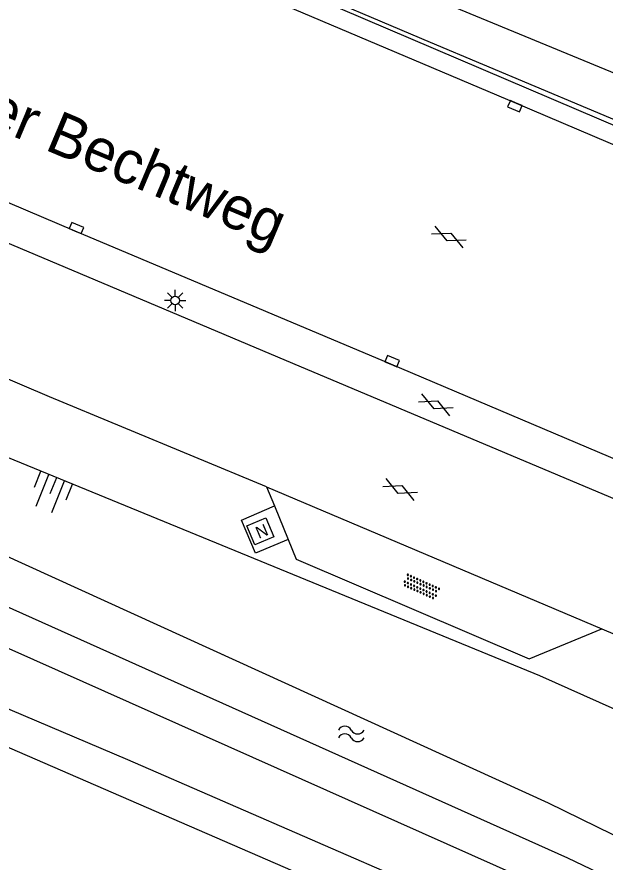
# Model space of a CAD drawing. Extents: x 136000 to 138005, y 398500 to 400500.
# Drawn here: x 136474.73 to 136509.2, y 399012.55 to 399062.04 of the extents above; entities that cross this region are included whole.
import ezdxf

# ---------------------------------------------------------------- set-up
doc = ezdxf.new("R2010")
doc.units = 0
for name, color, linetype in [('gg-afsc-faunaraster', 7, 'Continuous'), ('gg-anno-openbare ruimte label', 7, 'Continuous'), ('gg-knt-BGT kruinlijn', 7, 'Continuous'), ('gg-knt-verharding', 7, 'Continuous'), ('gg-kntw-bovenkant insteek waterloop', 7, 'Continuous'), ('gg-kntw-waterlijn', 7, 'Continuous'), ('gt-knt-geleideconstructie', 7, 'Continuous'), ('gt-symb-gesloten verharding', 7, 'Continuous'), ('gt-symb-kolk', 7, 'Continuous'), ('gt-symb-lichtmast', 7, 'Continuous'), ('gt-symb-nortonput', 7, 'Continuous'), ('gt-symb-overige verharding', 7, 'Continuous'), ('gt-symb-talud symbool', 7, 'Continuous'), ('gt-symb-watersymbool', 7, 'Continuous')]:
    doc.layers.add(name, color=color, linetype=linetype)

# ---------------------------------------------------------------- blocks, each defined once
blk = doc.blocks.new('gt0-LMAST')
at = {"layer": 'gt-symb-lichtmast'}
for p, q in [((-0.005, 0.246), (-0.005, 0.621)), ((-0.182, 0.173), (-0.447, 0.438)), ((0.172, 0.173), (0.437, 0.438)), ((-0.255, -0.004), (-0.63, -0.004)), ((-0.182, -0.181), (-0.447, -0.446)), ((-0.005, -0.254), (-0.005, -0.629)), ((0.437, -0.446), (0.172, -0.181)), ((0.245, -0.004), (0.62, -0.004))]:
    blk.add_line(p, q, dxfattribs=at)
blk.add_circle((-0.005, -0.004), 0.25, dxfattribs=at)
blk = doc.blocks.new('gt0-GESVH1')
at = {"layer": 'gt-symb-gesloten verharding'}
for p, q in [((-0.992, -0.261), (0.008, 0.239)), ((0.008, -0.261), (-0.992, 0.239)), ((0.008, 0.239), (1.008, -0.261)), ((1.008, 0.239), (0.008, -0.261))]:
    blk.add_line(p, q, dxfattribs=at)
blk = doc.blocks.new('gt0-KOLK')
at = {"layer": 'gt-symb-kolk'}
blk.add_lwpolyline([(0, 0), (0.375, 0), (0.375, 0.4), (-0.375, 0.4), (-0.375, 0), (0, 0)], dxfattribs=at)
blk = doc.blocks.new('gt0-OVH')
at = {"layer": 'gt-symb-overige verharding'}
for points in [[(-0.972, 0.298), (-0.967, 0.308), (-0.965, 0.319), (-0.966, 0.33), (-0.971, 0.34), (-0.978, 0.348), (-0.988, 0.353), (-0.999, 0.355), (-1.01, 0.354), (-1.02, 0.349), (-1.028, 0.342), (-1.033, 0.332), (-1.035, 0.321), (-1.034, 0.31), (-1.029, 0.3), (-1.022, 0.292), (-1.012, 0.287), (-1.001, 0.285), (-0.99, 0.286), (-0.98, 0.291)], [(-0.872, 0.106), (-0.867, 0.116), (-0.865, 0.126), (-0.866, 0.137), (-0.871, 0.147), (-0.878, 0.156), (-0.888, 0.161), (-0.899, 0.163), (-0.91, 0.162), (-0.92, 0.157), (-0.928, 0.15), (-0.933, 0.14), (-0.935, 0.129), (-0.934, 0.118), (-0.929, 0.108), (-0.922, 0.1), (-0.912, 0.095), (-0.901, 0.092), (-0.89, 0.094), (-0.88, 0.098)], [(-0.772, 0.298), (-0.767, 0.308), (-0.765, 0.319), (-0.766, 0.33), (-0.771, 0.34), (-0.778, 0.348), (-0.788, 0.353), (-0.799, 0.355), (-0.81, 0.354), (-0.82, 0.349), (-0.828, 0.342), (-0.833, 0.332), (-0.835, 0.321), (-0.834, 0.31), (-0.829, 0.3), (-0.822, 0.292), (-0.812, 0.287), (-0.801, 0.285), (-0.79, 0.286), (-0.78, 0.291)], [(-0.672, 0.106), (-0.667, 0.116), (-0.665, 0.126), (-0.666, 0.137), (-0.671, 0.147), (-0.678, 0.156), (-0.688, 0.161), (-0.699, 0.163), (-0.71, 0.162), (-0.72, 0.157), (-0.728, 0.15), (-0.733, 0.14), (-0.735, 0.129), (-0.734, 0.118), (-0.729, 0.108), (-0.722, 0.1), (-0.712, 0.095), (-0.701, 0.092), (-0.69, 0.094), (-0.68, 0.098)], [(-0.572, 0.298), (-0.567, 0.308), (-0.565, 0.319), (-0.566, 0.33), (-0.571, 0.34), (-0.578, 0.348), (-0.588, 0.353), (-0.599, 0.355), (-0.61, 0.354), (-0.62, 0.349), (-0.628, 0.342), (-0.633, 0.332), (-0.635, 0.321), (-0.634, 0.31), (-0.629, 0.3), (-0.622, 0.292), (-0.612, 0.287), (-0.601, 0.285), (-0.59, 0.286), (-0.58, 0.291)], [(-0.472, 0.106), (-0.467, 0.116), (-0.465, 0.126), (-0.466, 0.137), (-0.471, 0.147), (-0.478, 0.156), (-0.488, 0.161), (-0.499, 0.163), (-0.51, 0.162), (-0.52, 0.157), (-0.528, 0.15), (-0.533, 0.14), (-0.535, 0.129), (-0.534, 0.118), (-0.529, 0.108), (-0.522, 0.1), (-0.512, 0.095), (-0.501, 0.092), (-0.49, 0.094), (-0.48, 0.098)], [(-0.372, 0.298), (-0.367, 0.308), (-0.365, 0.319), (-0.366, 0.33), (-0.371, 0.34), (-0.378, 0.348), (-0.388, 0.353), (-0.399, 0.355), (-0.41, 0.354), (-0.42, 0.349), (-0.428, 0.342), (-0.433, 0.332), (-0.435, 0.321), (-0.434, 0.31), (-0.429, 0.3), (-0.422, 0.292), (-0.412, 0.287), (-0.401, 0.285), (-0.39, 0.286), (-0.38, 0.291)], [(-0.272, 0.106), (-0.267, 0.116), (-0.265, 0.126), (-0.266, 0.137), (-0.271, 0.147), (-0.278, 0.156), (-0.288, 0.161), (-0.299, 0.163), (-0.31, 0.162), (-0.32, 0.157), (-0.328, 0.15), (-0.333, 0.14), (-0.335, 0.129), (-0.334, 0.118), (-0.329, 0.108), (-0.322, 0.1), (-0.312, 0.095), (-0.301, 0.092), (-0.29, 0.094), (-0.28, 0.098)], [(-0.172, 0.298), (-0.167, 0.308), (-0.165, 0.319), (-0.166, 0.33), (-0.171, 0.34), (-0.178, 0.348), (-0.188, 0.353), (-0.199, 0.355), (-0.21, 0.354), (-0.22, 0.349), (-0.228, 0.342), (-0.233, 0.332), (-0.235, 0.321), (-0.234, 0.31), (-0.229, 0.3), (-0.222, 0.292), (-0.212, 0.287), (-0.201, 0.285), (-0.19, 0.286), (-0.18, 0.291)], [(-0.072, 0.106), (-0.067, 0.116), (-0.065, 0.126), (-0.066, 0.137), (-0.071, 0.147), (-0.078, 0.156), (-0.088, 0.161), (-0.099, 0.163), (-0.11, 0.162), (-0.12, 0.157), (-0.128, 0.15), (-0.133, 0.14), (-0.135, 0.129), (-0.134, 0.118), (-0.129, 0.108), (-0.122, 0.1), (-0.112, 0.095), (-0.101, 0.092), (-0.09, 0.094), (-0.08, 0.098)], [(0.028, 0.298), (0.033, 0.308), (0.035, 0.319), (0.034, 0.33), (0.029, 0.34), (0.022, 0.348), (0.012, 0.353), (0.001, 0.355), (-0.01, 0.354), (-0.02, 0.349), (-0.028, 0.342), (-0.033, 0.332), (-0.035, 0.321), (-0.034, 0.31), (-0.029, 0.3), (-0.022, 0.292), (-0.012, 0.287), (-0.001, 0.285), (0.01, 0.286), (0.02, 0.291)], [(0.128, 0.106), (0.133, 0.116), (0.135, 0.126), (0.134, 0.137), (0.129, 0.147), (0.122, 0.156), (0.112, 0.161), (0.101, 0.163), (0.09, 0.162), (0.08, 0.157), (0.072, 0.15), (0.067, 0.14), (0.065, 0.129), (0.066, 0.118), (0.071, 0.108), (0.078, 0.1), (0.088, 0.095), (0.099, 0.092), (0.11, 0.094), (0.12, 0.098)], [(0.228, 0.298), (0.233, 0.308), (0.235, 0.319), (0.234, 0.33), (0.229, 0.34), (0.222, 0.348), (0.212, 0.353), (0.201, 0.355), (0.19, 0.354), (0.18, 0.349), (0.172, 0.342), (0.167, 0.332), (0.165, 0.321), (0.166, 0.31), (0.171, 0.3), (0.178, 0.292), (0.188, 0.287), (0.199, 0.285), (0.21, 0.286), (0.22, 0.291)], [(0.328, 0.106), (0.333, 0.116), (0.335, 0.126), (0.334, 0.137), (0.329, 0.147), (0.322, 0.156), (0.312, 0.161), (0.301, 0.163), (0.29, 0.162), (0.28, 0.157), (0.272, 0.15), (0.267, 0.14), (0.265, 0.129), (0.266, 0.118), (0.271, 0.108), (0.278, 0.1), (0.288, 0.095), (0.299, 0.092), (0.31, 0.094), (0.32, 0.098)], [(0.428, 0.298), (0.433, 0.308), (0.435, 0.319), (0.434, 0.33), (0.429, 0.34), (0.422, 0.348), (0.412, 0.353), (0.401, 0.355), (0.39, 0.354), (0.38, 0.349), (0.372, 0.342), (0.367, 0.332), (0.365, 0.321), (0.366, 0.31), (0.371, 0.3), (0.378, 0.292), (0.388, 0.287), (0.399, 0.285), (0.41, 0.286), (0.42, 0.291)], [(0.528, 0.106), (0.533, 0.116), (0.535, 0.126), (0.534, 0.137), (0.529, 0.147), (0.522, 0.156), (0.512, 0.161), (0.501, 0.163), (0.49, 0.162), (0.48, 0.157), (0.472, 0.15), (0.467, 0.14), (0.465, 0.129), (0.466, 0.118), (0.471, 0.108), (0.478, 0.1), (0.488, 0.095), (0.499, 0.092), (0.51, 0.094), (0.52, 0.098)], [(0.628, 0.298), (0.633, 0.308), (0.635, 0.319), (0.634, 0.33), (0.629, 0.34), (0.622, 0.348), (0.612, 0.353), (0.601, 0.355), (0.59, 0.354), (0.58, 0.349), (0.572, 0.342), (0.567, 0.332), (0.565, 0.321), (0.566, 0.31), (0.571, 0.3), (0.578, 0.292), (0.588, 0.287), (0.599, 0.285), (0.61, 0.286), (0.62, 0.291)], [(0.728, 0.106), (0.733, 0.116), (0.735, 0.126), (0.734, 0.137), (0.729, 0.147), (0.722, 0.156), (0.712, 0.161), (0.701, 0.163), (0.69, 0.162), (0.68, 0.157), (0.672, 0.15), (0.667, 0.14), (0.665, 0.129), (0.666, 0.118), (0.671, 0.108), (0.678, 0.1), (0.688, 0.095), (0.699, 0.092), (0.71, 0.094), (0.72, 0.098)], [(0.828, 0.298), (0.833, 0.308), (0.835, 0.319), (0.834, 0.33), (0.829, 0.34), (0.822, 0.348), (0.812, 0.353), (0.801, 0.355), (0.79, 0.354), (0.78, 0.349), (0.772, 0.342), (0.767, 0.332), (0.765, 0.321), (0.766, 0.31), (0.771, 0.3), (0.778, 0.292), (0.788, 0.287), (0.799, 0.285), (0.81, 0.286), (0.82, 0.291)], [(0.928, 0.106), (0.933, 0.116), (0.935, 0.126), (0.934, 0.137), (0.929, 0.147), (0.922, 0.156), (0.912, 0.161), (0.901, 0.163), (0.89, 0.162), (0.88, 0.157), (0.872, 0.15), (0.867, 0.14), (0.865, 0.129), (0.866, 0.118), (0.871, 0.108), (0.878, 0.1), (0.888, 0.095), (0.899, 0.092), (0.91, 0.094), (0.92, 0.098)], [(1.028, 0.298), (1.033, 0.308), (1.035, 0.319), (1.034, 0.33), (1.029, 0.34), (1.022, 0.348), (1.012, 0.353), (1.001, 0.355), (0.99, 0.354), (0.98, 0.349), (0.972, 0.342), (0.967, 0.332), (0.965, 0.321), (0.966, 0.31), (0.971, 0.3), (0.978, 0.292), (0.988, 0.287), (0.999, 0.285), (1.01, 0.286), (1.02, 0.291)], [(-0.972, -0.142), (-0.967, -0.132), (-0.965, -0.121), (-0.966, -0.11), (-0.971, -0.1), (-0.978, -0.092), (-0.988, -0.087), (-0.999, -0.085), (-1.01, -0.086), (-1.02, -0.091), (-1.028, -0.098), (-1.033, -0.108), (-1.035, -0.119), (-1.034, -0.13), (-1.029, -0.14), (-1.022, -0.148), (-1.012, -0.153), (-1.001, -0.155), (-0.99, -0.154), (-0.98, -0.149)], [(-0.872, -0.334), (-0.867, -0.324), (-0.865, -0.314), (-0.866, -0.303), (-0.871, -0.293), (-0.878, -0.284), (-0.888, -0.279), (-0.899, -0.277), (-0.91, -0.278), (-0.92, -0.283), (-0.928, -0.29), (-0.933, -0.3), (-0.935, -0.311), (-0.934, -0.322), (-0.929, -0.332), (-0.922, -0.34), (-0.912, -0.345), (-0.901, -0.348), (-0.89, -0.346), (-0.88, -0.342)], [(-0.772, -0.142), (-0.767, -0.132), (-0.765, -0.121), (-0.766, -0.11), (-0.771, -0.1), (-0.778, -0.092), (-0.788, -0.087), (-0.799, -0.085), (-0.81, -0.086), (-0.82, -0.091), (-0.828, -0.098), (-0.833, -0.108), (-0.835, -0.119), (-0.834, -0.13), (-0.829, -0.14), (-0.822, -0.148), (-0.812, -0.153), (-0.801, -0.155), (-0.79, -0.154), (-0.78, -0.149)], [(-0.672, -0.334), (-0.667, -0.324), (-0.665, -0.314), (-0.666, -0.303), (-0.671, -0.293), (-0.678, -0.284), (-0.688, -0.279), (-0.699, -0.277), (-0.71, -0.278), (-0.72, -0.283), (-0.728, -0.29), (-0.733, -0.3), (-0.735, -0.311), (-0.734, -0.322), (-0.729, -0.332), (-0.722, -0.34), (-0.712, -0.345), (-0.701, -0.348), (-0.69, -0.346), (-0.68, -0.342)], [(-0.572, -0.142), (-0.567, -0.132), (-0.565, -0.121), (-0.566, -0.11), (-0.571, -0.1), (-0.578, -0.092), (-0.588, -0.087), (-0.599, -0.085), (-0.61, -0.086), (-0.62, -0.091), (-0.628, -0.098), (-0.633, -0.108), (-0.635, -0.119), (-0.634, -0.13), (-0.629, -0.14), (-0.622, -0.148), (-0.612, -0.153), (-0.601, -0.155), (-0.59, -0.154), (-0.58, -0.149)], [(-0.472, -0.334), (-0.467, -0.324), (-0.465, -0.314), (-0.466, -0.303), (-0.471, -0.293), (-0.478, -0.284), (-0.488, -0.279), (-0.499, -0.277), (-0.51, -0.278), (-0.52, -0.283), (-0.528, -0.29), (-0.533, -0.3), (-0.535, -0.311), (-0.534, -0.322), (-0.529, -0.332), (-0.522, -0.34), (-0.512, -0.345), (-0.501, -0.348), (-0.49, -0.346), (-0.48, -0.342)], [(-0.372, -0.142), (-0.367, -0.132), (-0.365, -0.121), (-0.366, -0.11), (-0.371, -0.1), (-0.378, -0.092), (-0.388, -0.087), (-0.399, -0.085), (-0.41, -0.086), (-0.42, -0.091), (-0.428, -0.098), (-0.433, -0.108), (-0.435, -0.119), (-0.434, -0.13), (-0.429, -0.14), (-0.422, -0.148), (-0.412, -0.153), (-0.401, -0.155), (-0.39, -0.154), (-0.38, -0.149)], [(-0.272, -0.334), (-0.267, -0.324), (-0.265, -0.314), (-0.266, -0.303), (-0.271, -0.293), (-0.278, -0.284), (-0.288, -0.279), (-0.299, -0.277), (-0.31, -0.278), (-0.32, -0.283), (-0.328, -0.29), (-0.333, -0.3), (-0.335, -0.311), (-0.334, -0.322), (-0.329, -0.332), (-0.322, -0.34), (-0.312, -0.345), (-0.301, -0.348), (-0.29, -0.346), (-0.28, -0.342)], [(-0.172, -0.142), (-0.167, -0.132), (-0.165, -0.121), (-0.166, -0.11), (-0.171, -0.1), (-0.178, -0.092), (-0.188, -0.087), (-0.199, -0.085), (-0.21, -0.086), (-0.22, -0.091), (-0.228, -0.098), (-0.233, -0.108), (-0.235, -0.119), (-0.234, -0.13), (-0.229, -0.14), (-0.222, -0.148), (-0.212, -0.153), (-0.201, -0.155), (-0.19, -0.154), (-0.18, -0.149)], [(-0.072, -0.334), (-0.067, -0.324), (-0.065, -0.314), (-0.066, -0.303), (-0.071, -0.293), (-0.078, -0.284), (-0.088, -0.279), (-0.099, -0.277), (-0.11, -0.278), (-0.12, -0.283), (-0.128, -0.29), (-0.133, -0.3), (-0.135, -0.311), (-0.134, -0.322), (-0.129, -0.332), (-0.122, -0.34), (-0.112, -0.345), (-0.101, -0.348), (-0.09, -0.346), (-0.08, -0.342)], [(0.028, -0.142), (0.033, -0.132), (0.035, -0.121), (0.034, -0.11), (0.029, -0.1), (0.022, -0.092), (0.012, -0.087), (0.001, -0.085), (-0.01, -0.086), (-0.02, -0.091), (-0.028, -0.098), (-0.033, -0.108), (-0.035, -0.119), (-0.034, -0.13), (-0.029, -0.14), (-0.022, -0.148), (-0.012, -0.153), (-0.001, -0.155), (0.01, -0.154), (0.02, -0.149)], [(0.128, -0.334), (0.133, -0.324), (0.135, -0.314), (0.134, -0.303), (0.129, -0.293), (0.122, -0.284), (0.112, -0.279), (0.101, -0.277), (0.09, -0.278), (0.08, -0.283), (0.072, -0.29), (0.067, -0.3), (0.065, -0.311), (0.066, -0.322), (0.071, -0.332), (0.078, -0.34), (0.088, -0.345), (0.099, -0.348), (0.11, -0.346), (0.12, -0.342)], [(0.228, -0.142), (0.233, -0.132), (0.235, -0.121), (0.234, -0.11), (0.229, -0.1), (0.222, -0.092), (0.212, -0.087), (0.201, -0.085), (0.19, -0.086), (0.18, -0.091), (0.172, -0.098), (0.167, -0.108), (0.165, -0.119), (0.166, -0.13), (0.171, -0.14), (0.178, -0.148), (0.188, -0.153), (0.199, -0.155), (0.21, -0.154), (0.22, -0.149)], [(0.328, -0.334), (0.333, -0.324), (0.335, -0.314), (0.334, -0.303), (0.329, -0.293), (0.322, -0.284), (0.312, -0.279), (0.301, -0.277), (0.29, -0.278), (0.28, -0.283), (0.272, -0.29), (0.267, -0.3), (0.265, -0.311), (0.266, -0.322), (0.271, -0.332), (0.278, -0.34), (0.288, -0.345), (0.299, -0.348), (0.31, -0.346), (0.32, -0.342)], [(0.428, -0.142), (0.433, -0.132), (0.435, -0.121), (0.434, -0.11), (0.429, -0.1), (0.422, -0.092), (0.412, -0.087), (0.401, -0.085), (0.39, -0.086), (0.38, -0.091), (0.372, -0.098), (0.367, -0.108), (0.365, -0.119), (0.366, -0.13), (0.371, -0.14), (0.378, -0.148), (0.388, -0.153), (0.399, -0.155), (0.41, -0.154), (0.42, -0.149)], [(0.528, -0.334), (0.533, -0.324), (0.535, -0.314), (0.534, -0.303), (0.529, -0.293), (0.522, -0.284), (0.512, -0.279), (0.501, -0.277), (0.49, -0.278), (0.48, -0.283), (0.472, -0.29), (0.467, -0.3), (0.465, -0.311), (0.466, -0.322), (0.471, -0.332), (0.478, -0.34), (0.488, -0.345), (0.499, -0.348), (0.51, -0.346), (0.52, -0.342)], [(0.628, -0.142), (0.633, -0.132), (0.635, -0.121), (0.634, -0.11), (0.629, -0.1), (0.622, -0.092), (0.612, -0.087), (0.601, -0.085), (0.59, -0.086), (0.58, -0.091), (0.572, -0.098), (0.567, -0.108), (0.565, -0.119), (0.566, -0.13), (0.571, -0.14), (0.578, -0.148), (0.588, -0.153), (0.599, -0.155), (0.61, -0.154), (0.62, -0.149)], [(0.728, -0.334), (0.733, -0.324), (0.735, -0.314), (0.734, -0.303), (0.729, -0.293), (0.722, -0.284), (0.712, -0.279), (0.701, -0.277), (0.69, -0.278), (0.68, -0.283), (0.672, -0.29), (0.667, -0.3), (0.665, -0.311), (0.666, -0.322), (0.671, -0.332), (0.678, -0.34), (0.688, -0.345), (0.699, -0.348), (0.71, -0.346), (0.72, -0.342)], [(0.828, -0.142), (0.833, -0.132), (0.835, -0.121), (0.834, -0.11), (0.829, -0.1), (0.822, -0.092), (0.812, -0.087), (0.801, -0.085), (0.79, -0.086), (0.78, -0.091), (0.772, -0.098), (0.767, -0.108), (0.765, -0.119), (0.766, -0.13), (0.771, -0.14), (0.778, -0.148), (0.788, -0.153), (0.799, -0.155), (0.81, -0.154), (0.82, -0.149)], [(0.928, -0.334), (0.933, -0.324), (0.935, -0.314), (0.934, -0.303), (0.929, -0.293), (0.922, -0.284), (0.912, -0.279), (0.901, -0.277), (0.89, -0.278), (0.88, -0.283), (0.872, -0.29), (0.867, -0.3), (0.865, -0.311), (0.866, -0.322), (0.871, -0.332), (0.878, -0.34), (0.888, -0.345), (0.899, -0.348), (0.91, -0.346), (0.92, -0.342)], [(1.028, -0.142), (1.033, -0.132), (1.035, -0.121), (1.034, -0.11), (1.029, -0.1), (1.022, -0.092), (1.012, -0.087), (1.001, -0.085), (0.99, -0.086), (0.98, -0.091), (0.972, -0.098), (0.967, -0.108), (0.965, -0.119), (0.966, -0.13), (0.971, -0.14), (0.978, -0.148), (0.988, -0.153), (0.999, -0.155), (1.01, -0.154), (1.02, -0.149)]]:
    blk.add_lwpolyline(points, close=True, dxfattribs=at)
blk = doc.blocks.new('gt0-NPUT')
at = {"layer": 'gt-symb-nortonput'}
blk.add_lwpolyline([(-0.566, -0.608), (-0.566, 0.592), (0.634, 0.592), (0.634, -0.608)], close=True, dxfattribs=at)
blk.add_text('N', height=0.7, dxfattribs=at).set_placement((-0.221, -0.381))
blk = doc.blocks.new('gt0-TALUD_1')
at = {"layer": 'gt-symb-talud symbool'}
for p, q in [((-1, -1), (-1, 0)), ((-0.5, -2), (-0.5, 0)), ((0, -1), (0, 0)), ((0.5, -2), (0.5, 0)), ((1, -1), (1, 0))]:
    blk.add_line(p, q, dxfattribs=at)
blk = doc.blocks.new('gt0-WA')
at = {"layer": 'gt-symb-watersymbool'}
for centre, start, end in [((-0.323, 0.022), 28.0725, 151.9275), ((0.427, 0.422), 208.0725, 331.9275), ((-0.323, -0.428), 28.0725, 151.9275), ((0.427, -0.028), 208.0725, 331.9275)]:
    blk.add_arc(centre, 0.425, start, end, dxfattribs=at)

msp = doc.modelspace()

# ---------------------------------------------------------------- linework, layer by layer
at = {"layer": 'gg-afsc-faunaraster'}
msp.add_lwpolyline([(136431.414, 399044.158), (136514.206, 399007.255), (136539.616, 398995.618), (136551.946, 399002.563)], dxfattribs=at)
at = {"layer": 'gg-knt-BGT kruinlijn'}
for points in [[(136537.056, 399044.242), (136526.798, 399048.395), (136489.576, 399064.287), (136457.475, 399077.937)], [(136551.946, 399002.563), (136549.024, 399003.963), (136505.377, 399023.463), (136448.758, 399046.668)]]:
    msp.add_lwpolyline(points, dxfattribs=at)
at = {"layer": 'gg-knt-verharding'}
for p, q in [((136489.365, 399034.534), (136509.014, 399026.216)), ((136489.365, 399034.534), (136489.825, 399033.408)), ((136489.825, 399033.408), (136490.629, 399031.44))]:
    msp.add_line(p, q, dxfattribs=at)
for points in [[(136457.058, 399076.956), (136464.669, 399073.703), (136485.501, 399064.84), (136503.99, 399057), (136520.243, 399050.08), (136534.913, 399043.847), (136538.526, 399042.268)], [(136558.328, 399015.106), (136555.989, 399016.185), (136544.437, 399021.341), (136529.311, 399027.847), (136514.561, 399034.12), (136496.641, 399041.7), (136478.15, 399049.499), (136445.546, 399063.373), (136443.73, 399064.107)], [(136442.845, 399062.044), (136454.925, 399056.934), (136490.874, 399041.766), (136515.717, 399031.307), (136533.222, 399023.897), (136552.453, 399015.442), (136557.468, 399013.147)], [(136489.365, 399034.534), (136476.65, 399039.8), (136448.346, 399051.86), (136443.289, 399054.125)], [(136490.629, 399031.44), (136488.713, 399030.633), (136487.894, 399032.578), (136489.825, 399033.408)], [(136490.629, 399031.44), (136491.095, 399030.3), (136504.745, 399024.46), (136509.014, 399026.216)], [(136509.014, 399026.216), (136536.298, 399014.645), (136550.071, 399008.452), (136554.52, 399006.433)]]:
    msp.add_lwpolyline(points, dxfattribs=at)
at = {"layer": 'gg-kntw-bovenkant insteek waterloop'}
for points in [[(136456.027, 399081.307), (136483.664, 399069.524), (136538.825, 399046.758)], [(136503.497, 399008.856), (136481.234, 399018.539), (136458.963, 399027.991), (136440.137, 399036.018), (136432.444, 399039.463)], [(136535.49, 399002.73), (136533.925, 399003.465), (136528.964, 399005.138), (136515.336, 399011.385), (136505.879, 399015.999), (136467.718, 399033.374), (136452.581, 399039.515)], [(136534.05, 398999.76), (136532.597, 399000.408), (136529.774, 399001.989), (136518.205, 399007.428), (136507.023, 399012.788), (136472.799, 399028.112), (136451.984, 399037.079), (136450.96, 399037.541)]]:
    msp.add_lwpolyline(points, dxfattribs=at)
at = {"layer": 'gg-kntw-waterlijn'}
msp.add_lwpolyline([(136433.215, 399037.446), (136470.279, 399020.988), (136505.43, 399005.746), (136508.859, 399004.032), (136514.765, 398996.792)], dxfattribs=at)
at = {"layer": 'gt-knt-geleideconstructie'}
msp.add_lwpolyline([(136468.308, 399073.551), (136473.169, 399071.426), (136479.347, 399068.85), (136485.441, 399066.249), (136490.374, 399064.219), (136498.946, 399060.57), (136511.22, 399055.405), (136518.535, 399052.255), (136523.469, 399050.183), (136528.37, 399048.125), (136532.036, 399046.546), (136535.68, 399044.884)], dxfattribs=at)

# ---------------------------------------------------------------- block references
at = {"layer": 'gt-symb-gesloten verharding'}
for p, rotation in [((136500.047, 399049.172), -24.131125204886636), ((136499.275, 399039.343), -24.131125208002), ((136497.179, 399034.385), -24.131125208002)]:
    msp.add_blockref('gt0-GESVH1', p, dxfattribs=dict(at, rotation=rotation))
at = {"layer": 'gt-symb-kolk'}
for p, rotation in [((136503.99, 399057), 156.92177859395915), ((136478.15, 399049.499), -22.897591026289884), ((136496.641, 399041.7), -22.950363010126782)]:
    msp.add_blockref('gt0-KOLK', p, dxfattribs=dict(at, rotation=rotation))
at = {"layer": 'gt-symb-lichtmast'}
msp.add_blockref('gt0-LMAST', (136484.01, 399045.441), dxfattribs=at)
at = {"layer": 'gt-symb-nortonput', "rotation": 22.82254064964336}
msp.add_blockref('gt0-NPUT', (136488.962, 399031.915), dxfattribs=at)
at = {"layer": 'gt-symb-overige verharding', "rotation": -24.131125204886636}
msp.add_blockref('gt0-OVH', (136498.42, 399028.672), dxfattribs=at)
at = {"layer": 'gt-symb-talud symbool', "xscale": 0.9999769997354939, "yscale": 0.999976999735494, "rotation": -22.02484593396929}
msp.add_blockref('gt0-TALUD_1', (136477.068, 399035.066), dxfattribs=at)
at = {"layer": 'gt-symb-watersymbool'}
msp.add_blockref('gt0-WA', (136494.271, 399020.06), dxfattribs=at)

# ---------------------------------------------------------------- texts
at = {"layer": 'gg-anno-openbare ruimte label'}
msp.add_text('Burgemeester Bechtweg', height=2.5, rotation=337.2, dxfattribs=at).set_placement((136456.085, 399062.792))

doc.saveas('drawing.dxf')
